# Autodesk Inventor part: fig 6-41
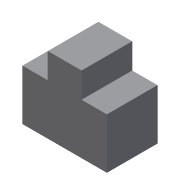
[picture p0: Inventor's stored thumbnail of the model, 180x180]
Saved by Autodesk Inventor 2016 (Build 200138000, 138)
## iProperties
Created: 2005-12
Part Number: fig 6-41
Document SubType Name: Modeling
Designer: CADCIM
Density: 1 g/cm^3
Material: Generic
Appearance: Default
Author: CADCIM
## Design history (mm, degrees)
sketch "Sketch1"
  geometry: L1 (10, 15)-(25, 15); L2 (25, 15)-(25, -15); L3 (25, -15)-(-25, -15); L4 (-25, -15)-(-25, 15); L5 (-25, 15)-(-10, 15); L6 (10, 15)-(10, 30); L7 (10, 30)-(-10, 30); L8 (-10, 30)-(-10, 15)
  constraints: 16 end point, 3 parallel, 3 perpendicular, 2 equal length, 1 collinear, 1 horizontal
  dimensions: "d0" = 50 distance of L2.end L3.end; "d2" = 30 distance of L1.end L2.end; "d3" = 15 distance of L1.start L1.end; "d11" = 15 distance of L7.end L5.end
extrude "Extrusion1" new body sketch "Sketch1" stored distance "d7" = 30; taper "d8" = 0 deg
body "Solid1"
